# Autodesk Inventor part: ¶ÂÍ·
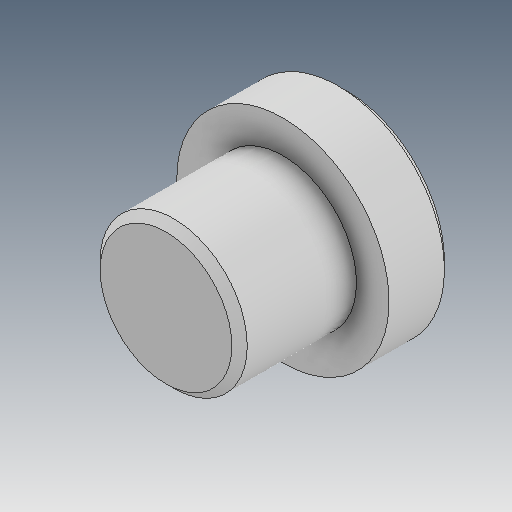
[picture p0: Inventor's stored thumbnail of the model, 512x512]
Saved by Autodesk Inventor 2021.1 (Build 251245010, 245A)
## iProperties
Created: 2019-04
Part Number: ¶ÂÍ·
Material: Ogólny
Document SubType Name: Modeling
Designer: user
Density: 1 g/cm^3
Appearance: Domyślna
Author: user
Revision Number: ÈÎºÎ
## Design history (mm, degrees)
feature "µ¹½Ç3"
node "Bryła1"
